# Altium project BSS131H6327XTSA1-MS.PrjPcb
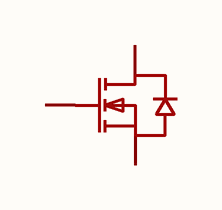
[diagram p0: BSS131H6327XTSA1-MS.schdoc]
1 sheet, 1 parts. Net scope: global (net labels, ports and power ports of the same name join across sheets).

## Sheet BSS131H6327XTSA1-MS.schdoc
size 127 x 101 mm

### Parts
Q?  bss131h6327xtsa1-ms  [SOT-23-3_L2.9-W1.3-P1.90-LS2.4-BR]  (value not drawn)

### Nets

Not connected (* = marked no-connect by the designer): Q? 1(G) 2(S) 3(D)

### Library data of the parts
Q? = bss131h6327xtsa1-ms: 数量:1个N沟道;漏源电压(Vdss):240V;连续漏极电流(Id):120mA;导通电阻(RDS(on)):7Ω@10V;耗散功率(Pd):1.25W;阈值电压(Vgs(th)):1.4V;; Manufacturer: MSKSEMI(美森科); AddInBom: yes; ModelId: c62791f0466c4ae2a892c056b845b0ca; ModelName: SOT-23-3P_L2.9-W1.3-H1.0-LS2.4-P0.95; ModelTransform: 98.425,114.173,0,180,0,0,0.0005,-0.0005,0; Number: 1个N沟道; Drain to Source Voltage: 240V; Current - Continuous Drain(Id): 120mA; RDS(on): 7Ω@10V; Pd - Power Dissipation: 1.25W; Gate Threshold Voltage (Vgs(th)): 1.4V; Gate Charge(Qg): 200pC@10V; Input Capacitance(Ciss): 70pF; Reverse Transfer Capacitance (Crss@Vds): 3pF; Type: N沟道; Output Capacitance(Coss): 7.5pF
